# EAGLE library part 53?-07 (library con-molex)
CONNECTOR wire to board 1.25 mm (.049 inch) pitch header
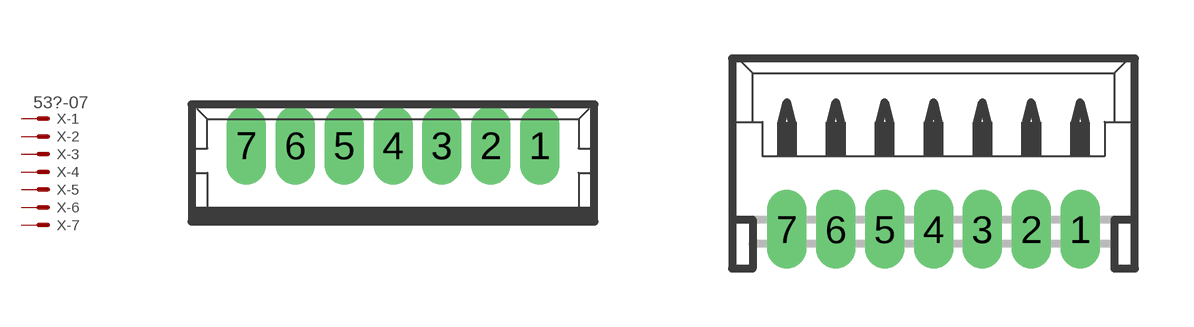
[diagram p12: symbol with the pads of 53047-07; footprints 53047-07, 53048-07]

Designator prefix X; gates -1=MV -2=M -3=M -4=M -5=M -6=M -7=M

## 53047-07 (MPN: 53047-0710-C; OC_FARNELL: 9732870; OC_NEWARK: 11M0149)  [53047-07]
1  -1:S  pas
2  -2:S  pas
3  -3:S  pas
4  -4:S  pas
5  -5:S  pas
6  -6:S  pas
7  -7:S  pas

## 53048-07 (MPN: 53048-0710; OC_FARNELL: 9732934; OC_NEWARK: 98K9835)  [53048-07]
Pads as for 53047-07

## 53261-07 (OC_FARNELL: 1125361; OC_NEWARK: unknown)  [53261-07]
Pads as for 53047-07

## 53398-07 (OC_FARNELL: 9786368; OC_NEWARK: unknown)  [53398-07]
Pads as for 53047-07

## Footprint 53047-07 (pad centres in mm)
CONNECTOR wire to board 1.25 mm (.049 inch) pitch header straight Sourcxe: http://www.molex.com/pdm_docs/sd/530470210_sd.pdf
drill 0.5 pad 0.698 long: 1 3.75,0.45; 2 2.5,0.45; 3 1.25,0.45; 4 0,0.45; 5 -1.25,0.45; 6 -2.5,0.45; 7 -3.75,0.45

## Footprint 53048-07 (pad centres in mm)
CONNECTOR wire to board 1.25 mm (.049 inch) pitch header right angle
drill 0.5 pad 0.698 long: 1 3.75,-1.25; 2 2.5,-1.25; 3 1.25,-1.25; 4 0,-1.25; 5 -1.25,-1.25; 6 -2.5,-1.25; 7 -3.75,-1.25

## Footprint 53261-07 (pad centres in mm)
CONNECTOR wire to board 1.25 mm (.049 inch) pitch header SMT right angle
smd 0.8 x 2: 1 3.75,-2.5; 2 2.5,-2.5; 3 1.25,-2.5; 4 0,-2.5; 5 -1.25,-2.5; 6 -2.5,-2.5; 7 -3.75,-2.5
smd 2.1 x 3: S1 6.25,0.625; S2 -6.25,0.625

## Footprint 53398-07 (pad centres in mm)
CONNECTOR wire to board 1.25 mm (.049 inch) pitch header SMT straight
smd 0.8 x 1.8: 1 3.75,-2.5; 2 2.5,-2.5; 3 1.25,-2.5; 4 0,-2.5; 5 -1.25,-2.5; 6 -2.5,-2.5; 7 -3.75,-2.5
smd 2.1 x 3: S1 6.25,0.625; S2 -6.25,0.625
